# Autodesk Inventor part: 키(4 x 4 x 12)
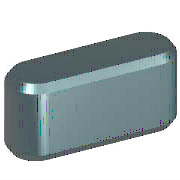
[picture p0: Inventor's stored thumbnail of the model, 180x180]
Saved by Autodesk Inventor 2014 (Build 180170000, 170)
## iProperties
IsCustomPart: 0
Created: 2009-02
Part Number: 키(4 x 4 x 12)
Material: 강철, 연강
Description: 키 및 해당 키홈
Document SubType Name: Modeling
Standard: KS B 1311
Designer: KYOUNG IL JANG
Standards Organization: KS
Language: ko-KR
Size Designation: 4 x 4 x 12
Categories: <MemberInstance><Categories><Category DisplayName="샤프트 부품" InternalName="7f7aeb1f-a693-4053-b835-cee3144e0d98" Mnemonic="SHFT"><Category DisplayName="키" Interna
Density: 7.86 g/cm^3
Mass: 1.38739 g
Surface Area: 1.94869 cm^2
Volume: 0.176513 cm^3
Appearance: 강철
Author: KYOUNG IL JANG
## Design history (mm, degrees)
workplane "Work Plane1"
workplane "Work Plane2"
sketch "스케치1"
  geometry: L1 (2, 2)-(10, 2); L2 (10, -2)-(2, -2); L3 (0, 9.4)-(0, -7.4) reference; L4 (-5, 0)-(30, 0) reference; L5 (12, 0)-(12, 7); A1 r 2 centre (2, 0) between (2, 2) and (2, -2); A2 r 2 centre (10, 0) between (10, -2) and (10, 2)
  constraints: 6 end point, 5 point on circle, 4 tangent, 3 point on line, 2 centre point, 1 horizontal, 1 parallel, 1 perpendicular
  dimensions: "d0" = 2 radius of A1 (= 0.5 x PB); "d13" = 2 radius of A2 (= 0.5 x PB); "d14" = 12 distance between parallel lines of L5 L3 (= NLG)
extrude "본체1" new body sketch "스케치1" taper "d3" = 0 deg; stored distance "d4" = 10
workplane "Work Plane3"
body "Solid1"
chamfer "모따기1" distance "d8" = 0.25 (= PHH); stored, may be unused: second distance "d9" = 0.25 (= PHH), angle "d15" = 45 deg
other parameters: "d1" = -2.5 (= -PNT), "d2" = 1.5 (= PH - PNT), "NLG" = 12 [user parameter; used in 3 equation terms], "PB" = 4 [user parameter; used in 2 equation terms], "PNT" = 2.5 [user parameter; used in 2 equation terms], "PH" = 4 [user parameter; used in 1 equation term], "PHH" = 0.25 [user parameter; used in 2 equation terms], "d10" = 0, "d16" = 0, "d17" = 0, "d18" = 0, "PLB2" = 12 (= NLG) [user parameter], "WDMAX" = 12 [user parameter], "PLB1" = 12 (= NLG) [user parameter], "RR" = 0.08 [user parameter], "PUEB" = 1.8 [user parameter]
